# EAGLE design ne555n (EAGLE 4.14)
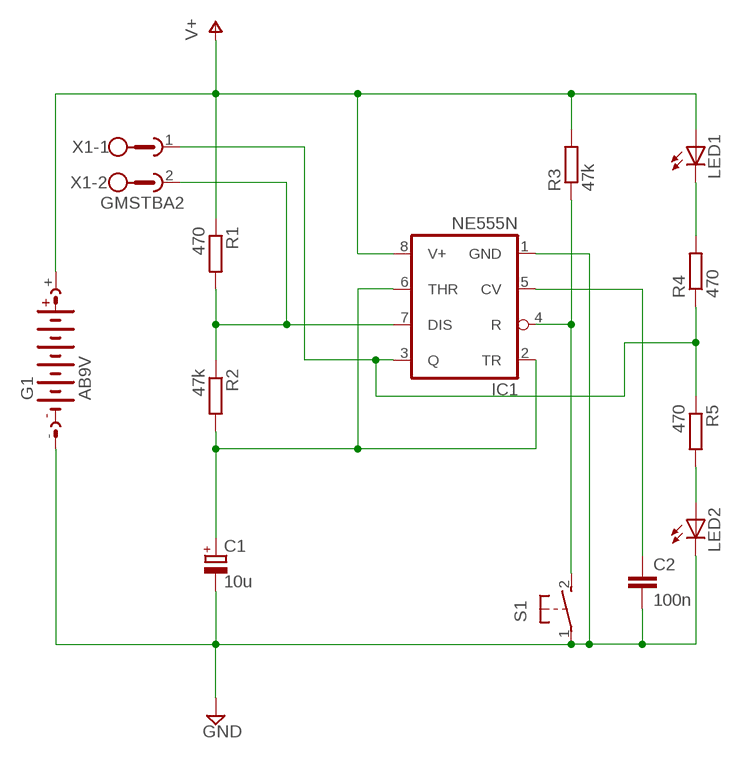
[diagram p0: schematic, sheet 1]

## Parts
C1  10u  CPOL-EUTT6D6  [TT5D6]
C2  100n  C-EU025-024X044  [C025-024X044]
G1  AB9V  [AB9V]
IC1  NE555N  [DIL08]
LED1  LED5MM  [LED5MM]
LED2  LED5MM  [LED5MM]
R1  470  R-EU_0207/10  [0207/10]
R2  47k  R-EU_0207/10  [0207/10]
R3  47k  R-EU_0207/10  [0207/10]
R4  470  R-EU_0207/10  [0207/10]
R5  470  R-EU_0207/10  [0207/10]
S1  31-XX  [B3F-31XX]
X1  GMSTBA2  [GMSTBA2]

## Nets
GND: C1.- C2.2 G1.- IC1.1(GND) LED2.K(C) S1.1(P)
N$1: C2.1 IC1.5(CV)
N$2: IC1.7(DIS) R1.2 R2.1 X1.2
N$3: C1.+ IC1.2(TR) IC1.6(THR) R2.2
N$4: IC1.4(R) R3.1 S1.2(S)
N$5: IC1.3(Q) R4.1 R5.1 X1.1
N$6: LED1.K(C) R4.2
N$7: LED2.A R5.2
V+: G1.+ IC1.8(V+) LED1.A R1.1 R3.2

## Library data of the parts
C1 = rcl:CPOL-EU: POLARIZED CAPACITOR, European symbol
C2 = rcl:C-EU: CAPACITOR, European symbol
G1 = battery:AB9V: 9-V BATTERY CLIP
IC1 = linear:*555: TIMER
LED1 LED2 = led:LED: LED
R1-R5 = rcl:R-EU_: RESISTOR, European symbol
S1 = switch-omron:31-XX: OMRON SWITCH
X1 = con-phoenix-508:GMSTBA2: PHOENIX

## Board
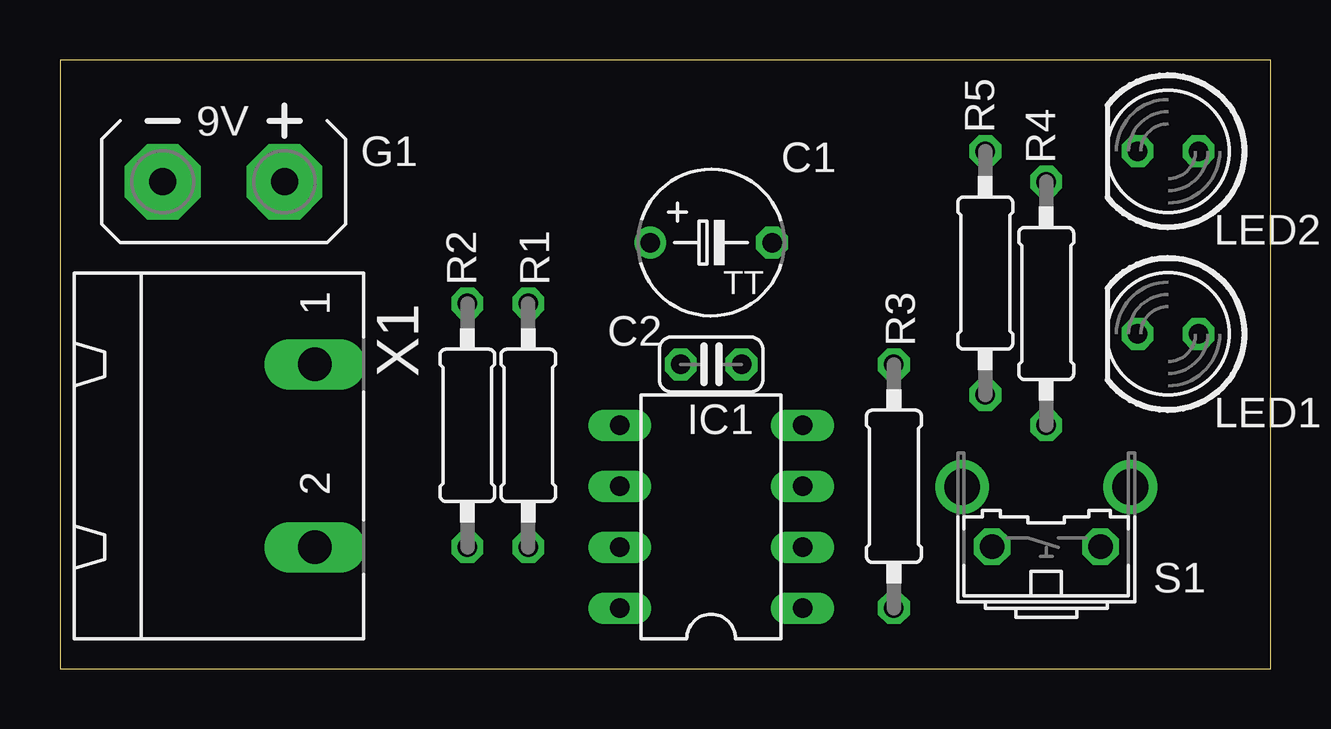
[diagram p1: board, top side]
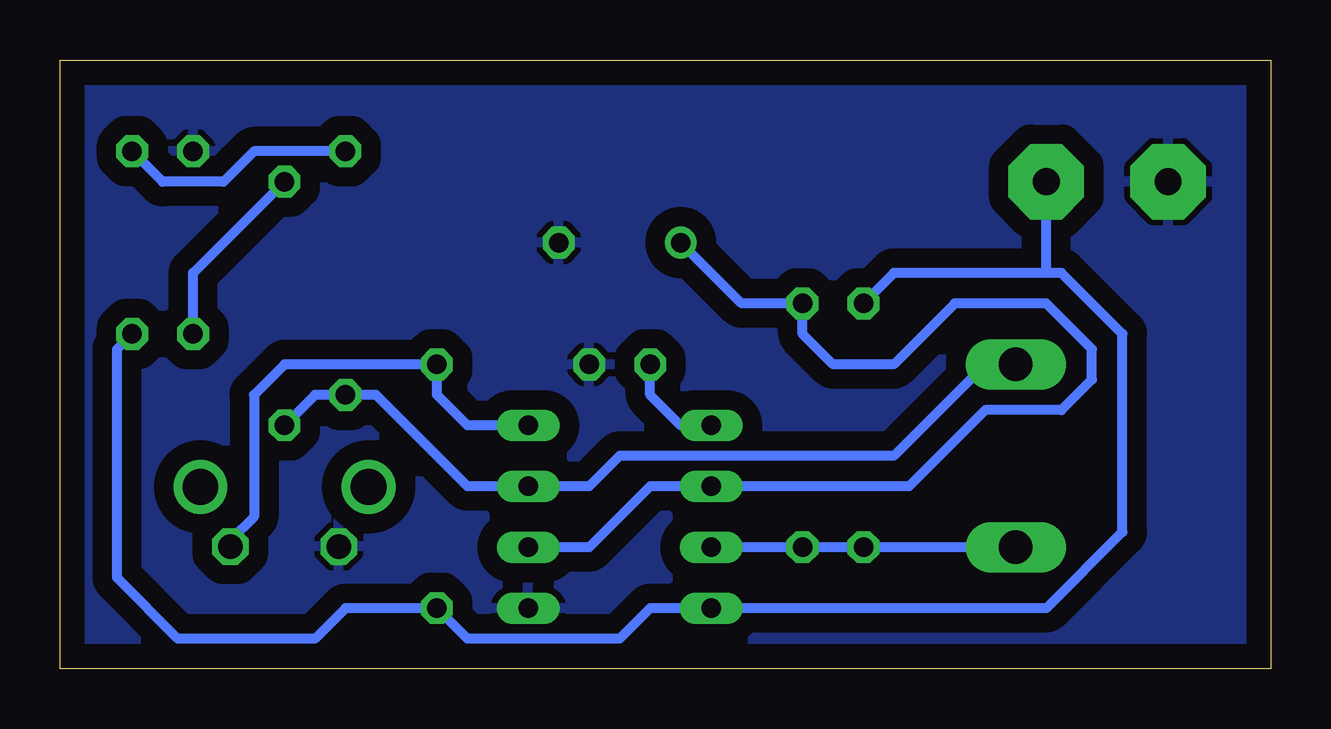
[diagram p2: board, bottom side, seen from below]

Size 50.47 x 25.39 mm. Coordinates in mm from the lower left corner, seen from the top.
Outline: 0,0 50.47,0 50.47,25.39 0,25.39 0,0
Copper layers (1*16): Top 0.035mm / dielectric 1.5mm / Bottom 0.035mm
Design rules "default": minimum track width 10mil, minimum drill 24mil, track to track 12mil, track to pad 12mil, pad to pad 12mil, via to via 12mil, smd to smd 12mil, copper to edge 40mil, drill to drill 8mil, minimum pad ring 10mil, minimum via ring 8mil, stop-mask expansion 4mil, vias tented up to drill 0mil, thermal gap 10mil

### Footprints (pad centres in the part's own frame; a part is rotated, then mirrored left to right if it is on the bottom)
TT5D6 = drill 0.813 round: + -2.54,0 | drill 0.813 octagon: - 2.54,0
C025-024X044 = drill 0.813 octagon: 1 -1.27,0; 2 1.27,0
AB9V = drill 1.118 pad 3.15 octagon: + 0,2.54; - 0,-2.54
DIL08 = drill 0.813 long: 1 -3.81,-3.81; 2 -1.27,-3.81; 3 1.27,-3.81; 4 3.81,-3.81; 5 3.81,3.81; 6 1.27,3.81; 7 -1.27,3.81; 8 -3.81,3.81
LED5MM = drill 0.813 octagon: A -1.27,0; K 1.27,0
0207/10 = drill 0.813 octagon: 1 -5.08,0; 2 5.08,0
B3F-31XX = drill 1.016 octagon: 1 -2.261,-1.245; 2 2.261,-1.245 | drill 1.499 pad 2.159 round: 3 -3.505,1.245; 4 3.505,1.245
GMSTBA2 = drill 1.397 long: 1 -3.81,5.08; 2 3.81,5.08

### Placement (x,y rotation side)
C1  27.14,17.77 0 top
C2  27.14,12.7 0 top
G1  6.82,20.31 270 top
IC1  27.14,6.34 90 top
LED1  46.19,13.97 180 top
LED2  46.19,21.58 180 top
R1  16.98,10.16 270 top
R2  19.52,10.16 90 top
R3  34.76,7.62 270 top
R4  41.11,15.24 90 top
R5  38.57,16.5 90 top
S1  41.11,6.34 0 top
X1  5.55,8.89 270 top

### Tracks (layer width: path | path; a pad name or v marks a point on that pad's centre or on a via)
GND
  pour Bottom (isolate 0.813): -0.17,25.39 50.63,25.39 50.63,-0.01 -0.17,-0.01
N$1
  Bottom 0.406: IC1.5 24.6,10.16 25.87,11.43 C2.1
N$2
  Bottom 0.406: X1.2 R1.2 R2.1 IC1.7
N$3
  Bottom 0.406: C1.+ 22.06,15.24 R2.2 19.52,13.97 18.25,12.7 15.71,12.7 13.17,15.24 9.36,15.24 7.46,13.33 7.46,12.06 8.73,10.79 11.9,10.79 15.08,7.62 IC1.6 25.87,7.62 28.41,5.08 IC1.2
N$4
  Bottom 0.406: IC1.4 33.49,10.16 34.76,11.43 R3.1 41.11,12.7 42.38,11.43 42.38,6.34 43.37,5.35 S1.2
N$5
  Bottom 0.406: X1.1 11.9,12.7 15.71,8.89 27.14,8.89 28.41,7.62 IC1.3 33.49,7.62 37.3,11.43 R5.1 39.84,11.43 R4.1
N$6
  Bottom 0.406: R4.2 44.92,16.5 LED1.K
N$7
  Bottom 0.406: LED2.A 46.19,20.31 43.65,20.31 42.38,21.58 R5.2
V+
  Bottom 0.406: LED1.A 48.09,13.33 48.09,3.8 45.55,1.27 39.84,1.27 38.57,2.54 R3.2 33.49,1.27 27.14,1.27 25.87,2.54 IC1.8 9.36,2.54 6.18,5.71 6.18,13.97 8.73,16.5 9.36,16.5 | 9.36,16.5 15.71,16.5 R1.1 | 9.36,16.5 G1.+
